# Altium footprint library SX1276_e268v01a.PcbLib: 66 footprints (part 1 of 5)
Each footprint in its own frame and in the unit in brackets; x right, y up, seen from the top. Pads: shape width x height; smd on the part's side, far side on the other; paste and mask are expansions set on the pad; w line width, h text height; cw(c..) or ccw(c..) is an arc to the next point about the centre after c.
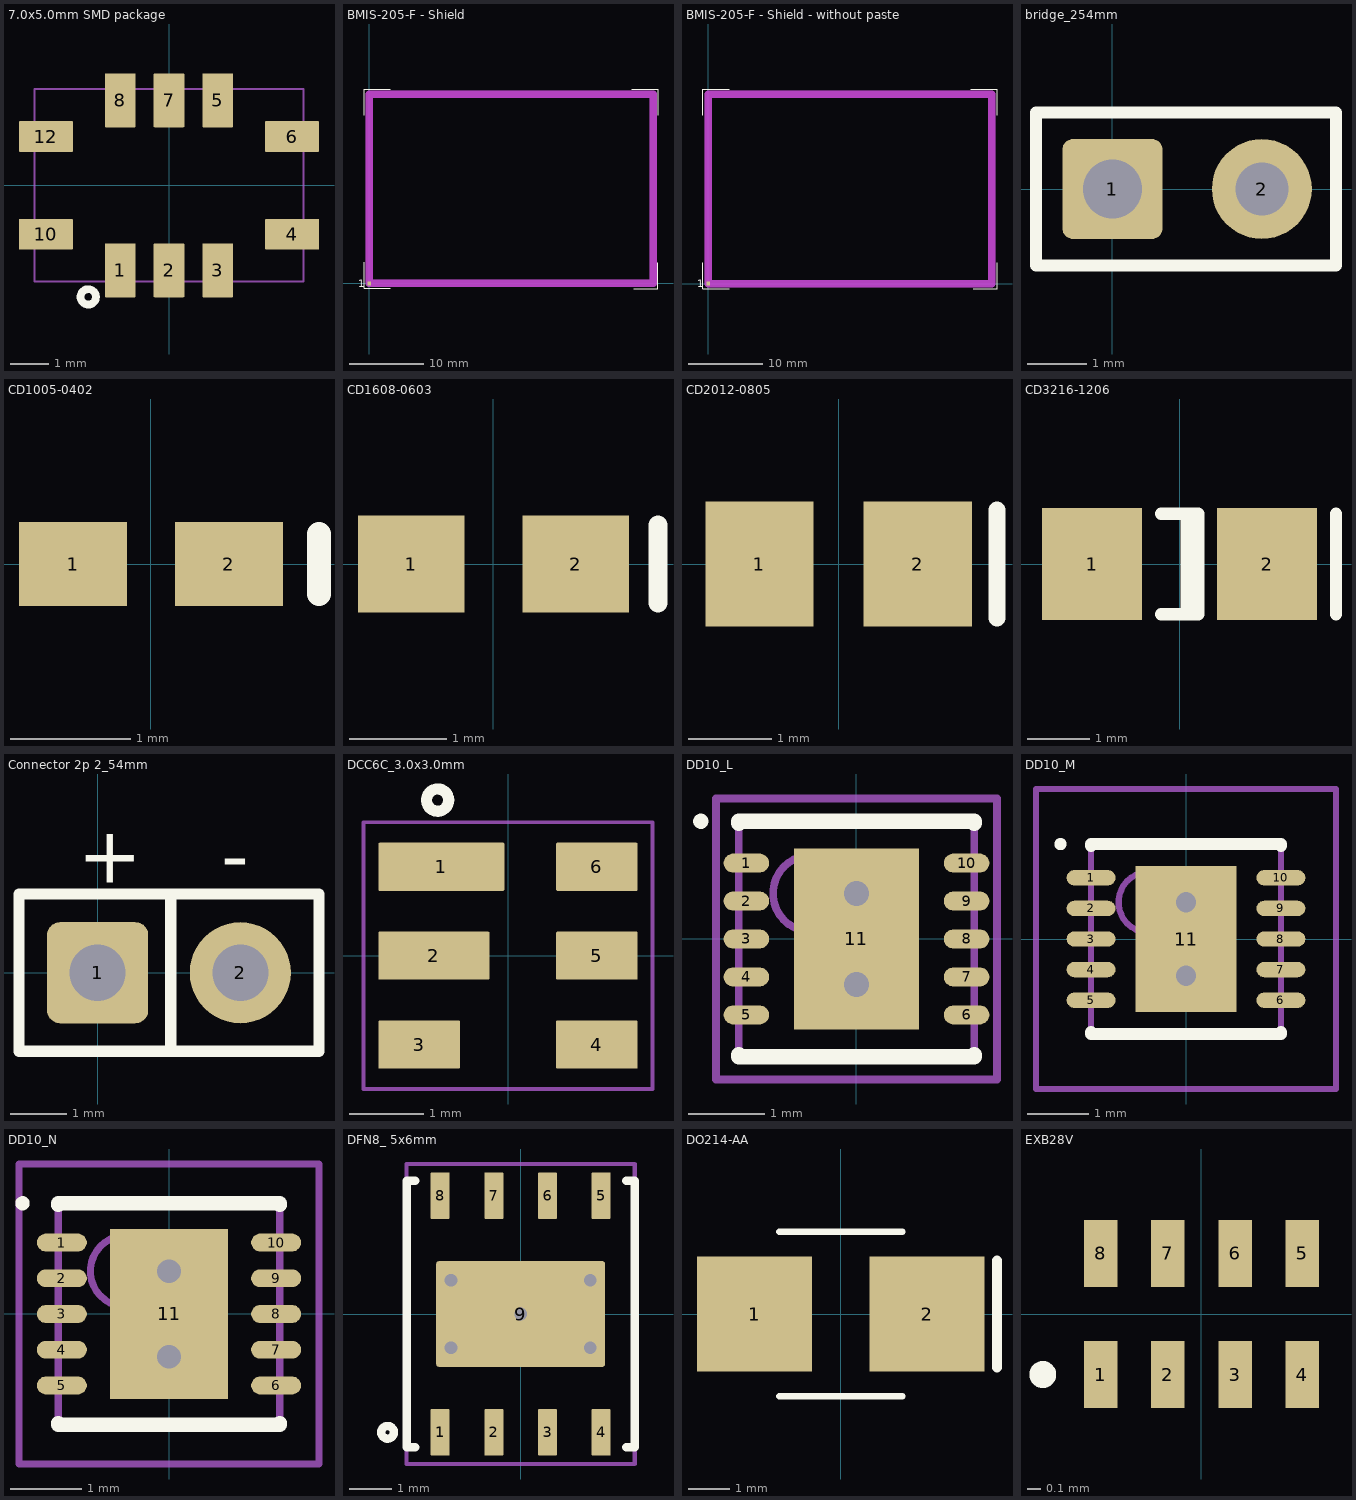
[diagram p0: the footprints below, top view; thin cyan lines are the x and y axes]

## 7.0x5.0mm SMD package [mm] "7.0x5.0mm SMD package - 10pins"
height 1.2
pads (10):
  rrect5% 0.8x1.4 smd mask+0.05: 1(-1.27,-2.21) 2(0,-2.21) 3(1.27,-2.21) 5(1.27,2.21) 7(0,2.21) 8(-1.27,2.21)
  rrect5% 1.4x0.8 smd mask+0.05: 4(3.2,-1.27) 6(3.2,1.27) 10(-3.2,-1.27) 12(-3.2,1.27)
Top Overlay:
  circle w0.2: c-2.1,-2.9 r0.2
Mechanical 15:
  lines w0.05: -3.5,-2.5 3.5,-2.5 3.5,2.5 -3.5,2.5 -3.5,-2.5
3D body: height 1, standoff 0, extent -3.5,-2.5 3.5,2.5

## BMIS-205-F - Shield [mm] "BMIS-205-F EMI Gasket - Standard Surface Mount Shields -  Laird Technologies"
height 6.5
pads (1):
  rect 0.5x0.5 smd paste-1 mask+0.05: 1(0,0)
Top Overlay:
  lines w0.1: -0.65,2.85 -0.65,-0.65 2.85,-0.65 ; -0.65,22.55 -0.65,26.05 2.85,26.05 ; 35.25,26.05 38.75,26.05 38.75,22.55 ; 35.5,-0.7 38.7,-0.7 38.7,2.8
  text "1" at -1.5,-0.5 h1
Top Paste:
  region: 20.65,-0.4 17.35,-0.4 17.35,0.6 20.65,0.6
  region: 32.65,-0.4 29.35,-0.4 29.35,0.6 32.65,0.6
  region: 26.65,-0.4 23.35,-0.4 23.35,0.6 26.65,0.6
  region: 14.65,-0.4 11.35,-0.4 11.35,0.6 14.65,0.6
  region: 8.65,-0.4 5.35,-0.4 5.35,0.6 8.65,0.6
  region: 38.4,-0.4 35.35,-0.4 35.35,0.6 38.4,0.6
  region: 2.65,-0.4 -0.4,-0.4 -0.4,0.6 2.65,0.6
  region: 2.65,24.8 -0.4,24.8 -0.4,25.8 2.65,25.8
  region: 38.4,24.8 35.35,24.8 35.35,25.8 38.4,25.8
  region: 8.65,24.8 5.35,24.8 5.35,25.8 8.65,25.8
  region: 14.65,24.8 11.35,24.8 11.35,25.8 14.65,25.8
  region: 26.65,24.8 23.35,24.8 23.35,25.8 26.65,25.8
  region: 32.65,24.8 29.35,24.8 29.35,25.8 32.65,25.8
  region: 20.65,24.8 17.35,24.8 17.35,25.8 20.65,25.8
  region: -0.4,22.7 -0.4,25.8 0.6,25.8 0.6,22.7
  region: -0.4,16.75 -0.4,20.05 0.6,20.05 0.6,16.75
  region: -0.4,10.75 -0.4,14.05 0.6,14.05 0.6,10.75
  region: -0.4,5.35 -0.4,8.05 0.6,8.05 0.6,5.35
  region: -0.4,-0.4 -0.4,2.65 0.6,2.65 0.6,-0.4
  region: 37.5,-0.4 37.5,2.65 38.5,2.65 38.5,-0.4
  region: 37.5,5.35 37.5,8.05 38.5,8.05 38.5,5.35
  region: 37.5,10.75 37.5,14.05 38.5,14.05 38.5,10.75
  region: 37.5,16.75 37.5,20.05 38.5,20.05 38.5,16.75
  region: 37.5,22.7 37.5,25.8 38.5,25.8 38.5,22.7
Top Solder:
  region: 37.5,22.7 37.5,25.8 38.5,25.8 38.5,22.7
  region: 37.5,16.75 37.5,20.05 38.5,20.05 38.5,16.75
  region: 37.5,10.75 37.5,14.05 38.5,14.05 38.5,10.75
  region: 37.5,5.35 37.5,8.05 38.5,8.05 38.5,5.35
  region: 37.5,-0.4 37.5,2.65 38.5,2.65 38.5,-0.4
  region: -0.4,-0.4 -0.4,2.65 0.6,2.65 0.6,-0.4
  region: -0.4,5.35 -0.4,8.05 0.6,8.05 0.6,5.35
  region: -0.4,10.75 -0.4,14.05 0.6,14.05 0.6,10.75
  region: -0.4,16.75 -0.4,20.05 0.6,20.05 0.6,16.75
  region: -0.4,22.7 -0.4,25.8 0.6,25.8 0.6,22.7
  region: 20.65,24.8 17.35,24.8 17.35,25.8 20.65,25.8
  region: 32.65,24.8 29.35,24.8 29.35,25.8 32.65,25.8
  region: 26.65,24.8 23.35,24.8 23.35,25.8 26.65,25.8
  region: 14.65,24.8 11.35,24.8 11.35,25.8 14.65,25.8
  region: 8.65,24.8 5.35,24.8 5.35,25.8 8.65,25.8
  region: 38.4,24.8 35.35,24.8 35.35,25.8 38.4,25.8
  region: 2.65,24.8 -0.4,24.8 -0.4,25.8 2.65,25.8
  region: 2.65,-0.4 -0.4,-0.4 -0.4,0.6 2.65,0.6
  region: 38.4,-0.4 35.35,-0.4 35.35,0.6 38.4,0.6
  region: 8.65,-0.4 5.35,-0.4 5.35,0.6 8.65,0.6
  region: 14.65,-0.4 11.35,-0.4 11.35,0.6 14.65,0.6
  region: 26.65,-0.4 23.35,-0.4 23.35,0.6 26.65,0.6
  region: 32.65,-0.4 29.35,-0.4 29.35,0.6 32.65,0.6
  region: 20.65,-0.4 17.35,-0.4 17.35,0.6 20.65,0.6
Mechanical 15 keep-out:
  lines w1: 0,0 38.1,0 38.1,25.4 0,25.4 0,0

## BMIS-205-F - Shield - without paste [mm] "BMIS-205-F EMI Gasket - Standard Surface Mount Shields -  Laird Technologies"
height 6.5
pads (1):
  rect 0.5x0.5 smd paste-1 mask+0.05: 1(0,0)
Top Overlay:
  lines w0.1: -0.7,2.8 -0.7,-0.7 2.8,-0.7 ; -0.7,22.6 -0.7,26.1 2.8,26.1 ; 35.3,26.1 38.8,26.1 38.8,22.6 ; 35.6,-0.7 38.8,-0.7 38.8,2.8
  text "1" at -1.5,-0.5 h1
Top Solder:
  region: 37.5,22.7 37.5,25.8 38.5,25.8 38.5,22.7
  region: 37.5,16.75 37.5,20.05 38.5,20.05 38.5,16.75
  region: 37.5,10.75 37.5,14.05 38.5,14.05 38.5,10.75
  region: 37.5,5.35 37.5,8.05 38.5,8.05 38.5,5.35
  region: 37.5,-0.4 37.5,2.65 38.5,2.65 38.5,-0.4
  region: -0.4,-0.4 -0.4,2.65 0.6,2.65 0.6,-0.4
  region: -0.4,5.35 -0.4,8.05 0.6,8.05 0.6,5.35
  region: -0.4,10.75 -0.4,14.05 0.6,14.05 0.6,10.75
  region: -0.4,16.75 -0.4,20.05 0.6,20.05 0.6,16.75
  region: -0.4,22.7 -0.4,25.8 0.6,25.8 0.6,22.7
  region: 20.65,24.8 17.35,24.8 17.35,25.8 20.65,25.8
  region: 32.65,24.8 29.35,24.8 29.35,25.8 32.65,25.8
  region: 26.65,24.8 23.35,24.8 23.35,25.8 26.65,25.8
  region: 14.65,24.8 11.35,24.8 11.35,25.8 14.65,25.8
  region: 8.65,24.8 5.35,24.8 5.35,25.8 8.65,25.8
  region: 38.4,24.8 35.35,24.8 35.35,25.8 38.4,25.8
  region: 2.65,24.8 -0.4,24.8 -0.4,25.8 2.65,25.8
  region: 2.65,-0.4 -0.4,-0.4 -0.4,0.6 2.65,0.6
  region: 38.4,-0.4 35.35,-0.4 35.35,0.6 38.4,0.6
  region: 8.65,-0.4 5.35,-0.4 5.35,0.6 8.65,0.6
  region: 14.65,-0.4 11.35,-0.4 11.35,0.6 14.65,0.6
  region: 26.65,-0.4 23.35,-0.4 23.35,0.6 26.65,0.6
  region: 32.65,-0.4 29.35,-0.4 29.35,0.6 32.65,0.6
  region: 20.65,-0.4 17.35,-0.4 17.35,0.6 20.65,0.6
Mechanical 15 keep-out:
  lines w1: 0,0 38.1,0 38.1,25.4 0,25.4 0,0

## bridge_254mm [mm] "Generic Bridge 2.54mm, 2 Leads 0.9mm;"
height 1
pads (2):
  rrect20% 1.7x1.7 hole 1 paste+0 mask+0.05: 1(0,0)
  round 1.7 hole 0.9 paste+0 mask+0.05: 2(2.54,0)
Top Overlay:
  lines w0.2: -1.3,-1.3 -1.3,1.3 3.8,1.3 3.8,-1.3 -1.3,-1.3

## CD1005-0402 [mm] "Chip Diode; Body 1.0 x 0.5 mm (LxW typ)"
height 0.6
pads (2):
  rect 0.9x0.7 smd mask+0.05: 1(-0.65,0) 2(0.65,0)
Top Overlay:
  lines w0.2: 1.4,-0.25 1.4,0.25

## CD1608-0603 [mm] "Chip Diode; Body 1.6 x 0.8 mm (LxW typ)"
height 0.85
pads (2):
  rect 1.1x1 smd mask+0.05: 1(-0.85,0) 2(0.85,0)
Top Overlay:
  lines w0.2: 1.7,-0.4 1.7,0.4

## CD2012-0805 [mm] "Chip Diode; Body 2.0 x 1.3 mm (LxW typ)"
height 1.1
pads (2):
  rect 1.3x1.5 smd mask+0.05: 1(-0.95,0) 2(0.95,0)
Top Overlay:
  lines w0.2: 1.9,-0.65 1.9,0.65

## CD3216-1206 [mm] "Chip Diode; Body 3.2 x 1.6 mm (LxW typ)"
height 1.35
pads (2):
  rect 1.6x1.8 smd mask+0.05: 1(-1.4,0) 2(1.4,0)
Top Overlay:
  lines w0.2: -0.3,-0.8 0.3,-0.8 0.3,0.8 -0.3,0.8 ; 0.11,-0.8 0.11,0.8 ; 2.5,-0.8 2.5,0.8

## Connector 2p 2_54mm [mm] "Generic connector 2.54mm, 2 Leads 1mm;"
height 1
pads (2):
  rrect25% 1.8x1.8 hole 1 paste+0 mask+0.05: 1(0,0)
  round 1.8 hole 1 paste+0 mask+0.05: 2(2.54,0)
Top Overlay:
  lines w0.2: 1.3,-1.4 1.3,1.4 ; -1.4,-1.4 -1.4,1.4 3.94,1.4 3.94,-1.4 -1.4,-1.4
  text "-" at 2.2,1.6 h1
  text "+" at -0.35,1.6 h1

## DCC6C_3.0x3.0mm [mm] "DCC6C footprint, 3.0x3.0mm"
height 1.1
pads (6):
  rrect5% 1.7x0.65 smd mask+0.05: 1(-0.9,1.2)
  rrect5% 1.5x0.65 smd mask+0.05: 2(-1,0)
  rrect5% 1.1x0.65 smd mask+0.05: 3(-1.2,-1.2) 4(1.2,-1.2) 5(1.2,0) 6(1.2,1.2)
Top Overlay:
  circle w0.15: c-0.95,2.1 r0.15
Mechanical 15:
  lines w0.05: -1.95,-1.8 -1.95,1.8 1.95,1.8 1.95,-1.8 -1.95,-1.8
3D body: height 1, standoff 0, extent -1.5,-1.5 1.5,1.5

## DD10_L [mm] "SON, 10-Leads, Body 3x3 mm, Pitch 0.5mm, IPC High Density"
height 0.8
pads (11):
  oval 0.6x0.25 smd: 1(-1.45,1) 2(-1.45,0.5) 3(-1.45,0) 4(-1.45,-0.5) 5(-1.45,-1) 6(1.45,-1) 7(1.45,-0.5) 8(1.45,0) 9(1.45,0.5) 10(1.45,1)
  rect 1.65x2.38 smd: 11(0,0)
via 0,0.6 diameter 0.66 hole 0.33
via 0,-0.6 diameter 0.66 hole 0.33
Top Overlay:
  circle w0.1: c-2.05,1.55 r0.05
  lines w0.2: -1.55,-1.525 -1.55,-1.55 1.55,-1.55 1.55,-1.525 ; -1.55,1.525 -1.55,1.55 1.55,1.55 1.55,1.525
Mechanical 13:
  circle w0.1: c-0.6,0.6 r0.5
  lines w0.1: -1.55,-1.55 1.55,-1.55 1.55,1.55 -1.55,1.55 -1.55,-1.55
Mechanical 15:
  lines w0.1: -0.5,0 0.5,0 ; 0,-0.5 0,0.5 ; -1.85,-1.85 1.85,-1.85 1.85,1.85 -1.85,1.85 -1.85,-1.85
3D body: height 0.8, standoff 0, extent -1.55,-1.55 1.55,1.55

## DD10_M [mm] "SON, 10-Leads, Body 3x3 mm, Pitch 0.5mm, IPC Low Density"
height 0.8
pads (11):
  oval 0.8x0.25 smd: 1(-1.55,1) 2(-1.55,0.5) 3(-1.55,0) 4(-1.55,-0.5) 5(-1.55,-1) 6(1.55,-1) 7(1.55,-0.5) 8(1.55,0) 9(1.55,0.5) 10(1.55,1)
  rect 1.65x2.38 smd: 11(0,0)
via 0,0.6 diameter 0.66 hole 0.33
via 0,-0.6 diameter 0.66 hole 0.33
Top Overlay:
  circle w0.1: c-2.05,1.55 r0.05
  lines w0.2: -1.55,-1.525 -1.55,-1.55 1.55,-1.55 1.55,-1.525 ; -1.55,1.525 -1.55,1.55 1.55,1.55 1.55,1.525
Mechanical 13:
  circle w0.1: c-0.6,0.6 r0.5
  lines w0.1: -1.55,-1.55 1.55,-1.55 1.55,1.55 -1.55,1.55 -1.55,-1.55
Mechanical 15:
  lines w0.1: -0.5,0 0.5,0 ; 0,-0.5 0,0.5 ; -2.45,-2.45 2.45,-2.45 2.45,2.45 -2.45,2.45 -2.45,-2.45
3D body: height 0.8, standoff 0, extent -1.55,-1.55 1.55,1.55

## DD10_N [mm] "SON, 10-Leads, Body 3x3 mm, Pitch 0.5mm, IPC Medium Density"
height 0.8
pads (11):
  oval 0.7x0.25 smd: 1(-1.5,1) 2(-1.5,0.5) 3(-1.5,0) 4(-1.5,-0.5) 5(-1.5,-1) 6(1.5,-1) 7(1.5,-0.5) 8(1.5,0) 9(1.5,0.5) 10(1.5,1)
  rect 1.65x2.38 smd: 11(0,0)
via 0,0.6 diameter 0.66 hole 0.33
via 0,-0.6 diameter 0.66 hole 0.33
Top Overlay:
  circle w0.1: c-2.05,1.55 r0.05
  lines w0.2: -1.55,-1.525 -1.55,-1.55 1.55,-1.55 1.55,-1.525 ; -1.55,1.525 -1.55,1.55 1.55,1.55 1.55,1.525
Mechanical 13:
  circle w0.1: c-0.6,0.6 r0.5
  lines w0.1: -1.55,-1.55 1.55,-1.55 1.55,1.55 -1.55,1.55 -1.55,-1.55
Mechanical 15:
  lines w0.1: -0.5,0 0.5,0 ; 0,-0.5 0,0.5 ; -2.1,-2.1 2.1,-2.1 2.1,2.1 -2.1,2.1 -2.1,-2.1
3D body: height 0.8, standoff 0, extent -1.55,-1.55 1.55,1.55

## DFN8_ 5x6mm [mm] "8 Leads, Body 5x6mm, pitch 1.27mm, DFN8"
height 0.9
pads (9):
  rrect10% 0.45x1.1 smd paste+0 mask+0.05: 1(-1.905,-2.8) 2(-0.635,-2.8) 3(0.635,-2.8) 4(1.905,-2.8) 5(1.905,2.8) 6(0.635,2.8) 7(-0.635,2.8) 8(-1.905,2.8)
  rrect5% 4x2.5 smd paste+0 mask+0.05: 9(0,0)
via -1.65,0.8 diameter 0.6 hole 0.3
via -1.65,-0.8 diameter 0.6 hole 0.3
via 0,0 diameter 0.6 hole 0.3
via 1.65,-0.8 diameter 0.6 hole 0.3
via 1.65,0.8 diameter 0.6 hole 0.3
Top Overlay:
  circle w0.2: c-3.15,-2.8 r0.15
  lines w0.2: -2.5,-3.15 -2.7,-3.15 -2.7,3.15 -2.5,3.15 ; 2.5,-3.15 2.7,-3.15 2.7,3.15 2.5,3.15
Top Paste:
  rectangle: -1.4,-0.8 1.4,0.8
Mechanical 15:
  lines w0.1: -2.7,-3.55 2.7,-3.55 2.7,3.55 -2.7,3.55 -2.7,-3.55
3D body: height 12, standoff 0, extent -2.5,-3 2.5,3

## DO214-AA [mm] "Chip Diode; Body 4.3 x3.6mm (LxW typ)"
height 1
pads (2):
  rect 2.8x2.8 smd mask+0.05: 1(-2.1,0) 2(2.1,0)
Top Overlay:
  lines w0.15: -1.5,-2 1.5,-2 ; -1.5,2 1.5,2
  lines w0.25: 3.8,-1.3 3.8,1.3

## EXB28V [mm] "Chip Resistor Array, (0402x4); SM; 8 Leads; Body 2.10 x 1.10 mm (LxW max)"
height 0.45
pads (8):
  rect 0.25x0.5 smd mask+0.05: 1(-0.75,-0.45) 2(-0.25,-0.45) 3(0.25,-0.45) 4(0.75,-0.45) 5(0.75,0.45) 6(0.25,0.45) 7(-0.25,0.45) 8(-0.75,0.45)
Top Overlay:
  circle w0.1: c-1.18,-0.45 r0.05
